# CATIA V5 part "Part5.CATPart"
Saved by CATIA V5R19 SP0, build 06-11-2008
Part number: Part5
Bounding box of the stored display mesh (mm): x -50 to 20, y -37.5 to 37.5, z -37.49 to 37.49
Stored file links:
  D:\thinkmotion-MPB\Dropbox\CIAO82010_JCF\BOUCHEFRA\580-bouchefra\Part5.CATPart
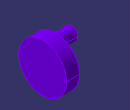
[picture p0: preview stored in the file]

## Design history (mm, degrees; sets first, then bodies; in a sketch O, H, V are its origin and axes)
Body1 (main body)
  Sketch1 on yz-plane, origin (0, 0, 0), H (0, 1, 0), V (0, 0, 1)
    circle A1 centre (0, 0) radius 37.5
    radius A1 = 37.5
  Pad1: profile Sketch1, direction (1, 0, 0), length 20
  Sketch2 on start face of Pad1, origin (0, 0, 0), H (0, -1, 0), V (0, 0, 1)
    circle A1 centre (25, 0) radius 10
    point P1 (25, 0)
    radius A1 = 10
    distance O P1 = 25
    coincidence: P1 H
  Pad2: profile Sketch2, direction (-1, 0, 0), length 50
